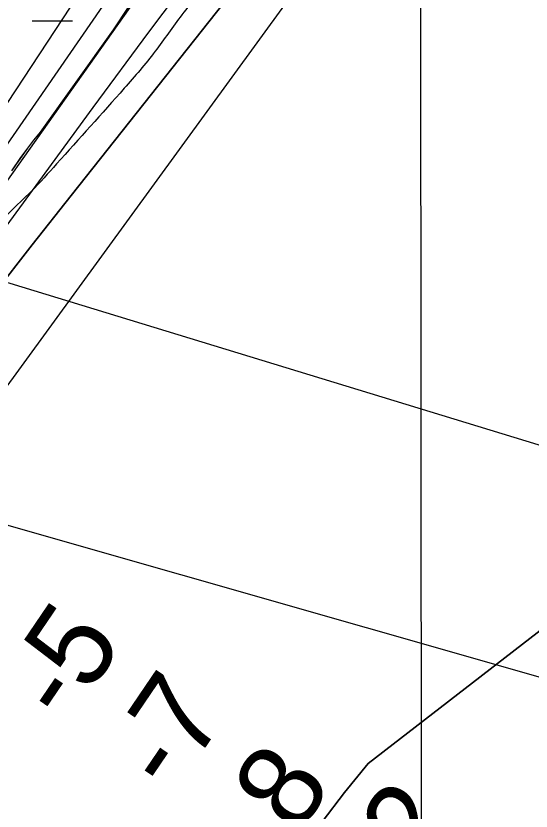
# Model space of a CAD drawing. Extents: x 3297735 to 3335592, y 670436 to 695807.
# Drawn here: x 3317296 to 3317704, y 689991 to 690622 of the extents above; entities that cross this region are included whole.
import ezdxf

# ---------------------------------------------------------------- set-up
doc = ezdxf.new("R2010")
doc.units = 0
for name, color, linetype in [('V-GRID-MAJR', 7, 'Continuous'), ('V-RIVR-EDGE', 7, 'Continuous'), ('V-RIVR-RANG', 7, 'Continuous'), ('V-SITE-VEGE', 7, 'Continuous'), ('V-TOPO-DPTH', 7, 'Continuous'), ('V-TOPO-MINR', 7, 'Continuous'), ('V-TOPO-WATR', 7, 'Continuous'), ('V-UTIL-LINE', 7, 'Continuous'), ('V-WETL-SWMP', 7, 'Continuous')]:
    doc.layers.add(name, color=color, linetype=linetype)

msp = doc.modelspace()

# ---------------------------------------------------------------- linework, layer by layer
at = {"layer": 'V-GRID-MAJR'}
msp.add_lwpolyline([(3317613.19, 694012.57), (3317614.99, 692249.17), (3317618.11, 689185.08), (3317621.45, 685897.36), (3317623.83, 683567.34), (3317626.56, 680885.93), (3317629.35, 678140.95), (3317631.33, 676194.39), (3317631.71, 675828.01)], dxfattribs=at)
at = {"layer": 'V-RIVR-EDGE'}
msp.add_spline([(3319555.14, 694014.55), (3319548.52, 694002.76), (3319539.36, 693985.79), (3319509.78, 693923.27), (3319496.46, 693903), (3319479.41, 693878.17), (3319464.01, 693854.58), (3319445.27, 693818.98), (3319424.44, 693775.51), (3319406.53, 693740.74), (3319395.69, 693713), (3319386.52, 693693.13), (3319372.79, 693671.61), (3319340.34, 693621.53), (3319316.61, 693580.14), (3319295.79, 693542.89), (3319282.06, 693520.96), (3319271.65, 693502.33), (3319267.89, 693489.49), (3319259.98, 693475.83), (3319250.42, 693465.08), (3319246.25, 693454.32), (3319237.93, 693442.32), (3319231.68, 693428.65), (3319225.43, 693414.99), (3319219.61, 693410.03), (3319205.47, 693391.42), (3319185.09, 693363.28), (3319164.7, 693327.69), (3319143.08, 693301.21), (3319109.39, 693253.21), (3319083.6, 693218.46), (3319061.14, 693187.85), (3319039.52, 693157.64), (3319018.29, 693123.29), (3318994.59, 693091.02), (3318949.68, 693031.86), (3318931.37, 693004.55), (3318913.08, 692981.38), (3318902.25, 692962.76), (3318892.68, 692944.55), (3318876.03, 692916.4), (3318861.86, 692887.84), (3318841.46, 692848.51), (3318822.29, 692807.53), (3318806.46, 692774.41), (3318803.1, 692758.66), (3318804.31, 692744.98), (3318808.02, 692734.61), (3318808.84, 692730.46), (3318817.11, 692725.47), (3318826.63, 692719.23), (3318832.83, 692713), (3318835.72, 692705.53), (3318835.27, 692692.27), (3318829.85, 692681.5), (3318819.88, 692669.09), (3318809.47, 692651.3), (3318783.24, 692602.87), (3318768.67, 692580.52), (3318760.79, 692575.98), (3318753.73, 692573.1), (3318747.11, 692573.94), (3318739.24, 692579.76), (3318735.53, 692585.58), (3318730.56, 692588.49), (3318721.44, 692588.1), (3318700.27, 692573.64), (3318679.48, 692549.66), (3318660.76, 692522.35), (3318646.6, 692493.37), (3318637.03, 692477.64), (3318624.96, 692456.95), (3318607.08, 692434.19), (3318599.98, 692413.49), (3318583.3, 692372.49), (3318565.82, 692342.28), (3318547.09, 692313.73), (3318534.2, 692295.52), (3318512.56, 692258.69), (3318488.02, 692224.76), (3318446.4, 692155.23), (3318418.11, 692112.61), (3318397.31, 692084.47), (3318386.91, 692066.68), (3318376.5, 692048.05), (3318354.44, 692011.22), (3318333.22, 691976.45), (3318316.13, 691940.02), (3318301.57, 691917.67), (3318275.38, 691884.99), (3318265.81, 691873), (3318250.82, 691844.85), (3318236.64, 691808.41), (3318222.07, 691781.09), (3318194.96, 691714.01), (3318179.96, 691684.2), (3318162.07, 691654.82), (3318140.84, 691619.64), (3318130.44, 691603.92), (3318120.89, 691595.24), (3318105.09, 691577.87), (3318090.12, 691558.42), (3318067.68, 691532.37), (3318043.56, 691501.75), (3318020.26, 691465.75), (3317998.21, 691433.06), (3317973.66, 691392.92), (3317962.42, 691371.81), (3317929.95, 691315.1), (3317907.9, 691282.41), (3317889.2, 691263.39), (3317870.48, 691238.16), (3317844.7, 691202.99), (3317833.05, 691186.02), (3317808.09, 691148.78), (3317780.64, 691109.47), (3317756.1, 691076.38), (3317731.98, 691045.35), (3317684.57, 690978.73), (3317668.76, 690954.73), (3317646.3, 690922.04), (3317635.48, 690907.15), (3317629.25, 690900.53), (3317620.1, 690889.36), (3317608.46, 690874.47), (3317601.4, 690867.03), (3317592.67, 690860.42), (3317585.59, 690845.93), (3317576.86, 690836), (3317565.64, 690821.11), (3317549.42, 690801.25), (3317522.4, 690767.75), (3317502.45, 690745), (3317489.97, 690727.62), (3317482.47, 690713.55), (3317479.54, 690701.12), (3317475.78, 690689.94), (3317474.94, 690683.31), (3317467.87, 690674.21), (3317451.65, 690653.94), (3317427.54, 690622.91), (3317406.33, 690593.95), (3317381.8, 690564.58), (3317328.18, 690504.62), (3317308.23, 690483.11), (3317290.78, 690466.16), (3317272.5, 690446.31), (3317248.81, 690422.74), (3317230.94, 690402.48), (3317202.23, 690356.54), (3317170.21, 690314.34), (3317129.47, 690266.36), (3317099.12, 690227.48), (3317085.82, 690212.59), (3317074.19, 690204.33), (3317063.38, 690189.85), (3317045.08, 690163.78), (3317020.95, 690128.61), (3316996.82, 690093.85), (3316970.63, 690059.1), (3316926.98, 690008.23), (3316891.65, 689970.6), (3316861.71, 689930.05), (3316828.03, 689887.86), (3316809.31, 689860.13), (3316797.25, 689841.93), (3316783.53, 689825.38), (3316737.37, 689762.08), (3316714.9, 689728.98), (3316681.64, 689687.61), (3316661.69, 689665.69), (3316647.97, 689646.66), (3316619.68, 689606.11), (3316602.63, 689581.28), (3316583.49, 689551.9), (3316563.93, 689519.62), (3316547.71, 689499.35), (3316541.89, 689491.9), (3316538.57, 689488.6), (3316532.31, 689474.1), (3316523.16, 689461.28), (3316509.03, 689445.15), (3316500.29, 689431.49), (3316493.22, 689419.9), (3316485.73, 689407.9), (3316486.11, 689397.12), (3316486.48, 689375.57), (3316487.29, 689371.01), (3316491.44, 689370.17), (3316493.5, 689366.43), (3316494.29, 689352.75), (3316496.75, 689341.56), (3316502.54, 689336.57), (3316504.2, 689334.08), (3316504.18, 689328.69), (3316501.27, 689325.8), (3316488.83, 689321.27), (3316487.17, 689319.61), (3316487.16, 689316.71), (3316492.96, 689316.7), (3316502.08, 689318.33), (3316508.3, 689318.32), (3316513.27, 689314.99), (3316516.58, 689314.98), (3316524.87, 689314.55), (3316535.62, 689303.33), (3316544.71, 689293.36), (3316545.54, 689290.04), (3316543.46, 689287.97), (3316525.66, 689296.72), (3316509.92, 689304.22), (3316502.06, 689307.14), (3316490.45, 689308.41), (3316482.58, 689308.02), (3316478.02, 689308.03), (3316473.47, 689311.77), (3316449.46, 689323.85), (3316424.59, 689324.74), (3316401.79, 689323.14), (3316381.47, 689318.22), (3316366.54, 689316.18), (3316352.85, 689311.24), (3316334.16, 689295.54), (3316302.2, 689277.79), (3316275.21, 689257.14), (3316266.49, 689249.28), (3316249.02, 689224.04), (3316230.28, 689191.76), (3316217.78, 689162.78), (3316200.69, 689125.93), (3316182.37, 689092.82), (3316162.8, 689054.73), (3316141.17, 689024.94), (3316114.57, 688996.41), (3316081.77, 688971.62), (3316036.89, 688926.14), (3316007.39, 688897.61), (3315987.04, 688880.67), (3315970.01, 688865.79), (3315959.63, 688858.77), (3315957.13, 688852.14), (3315955.46, 688848.42), (3315953.91, 688835.53)], degree=3, dxfattribs=at)
at = {"layer": 'V-SITE-VEGE'}
for p, q in [((3317385, 690629.03), (3317373.06, 690610.88)), ((3317373.06, 690610.88), (3317315.17, 690529.81)), ((3317315.17, 690529.81), (3317309.82, 690523.5)), ((3317309.82, 690523.5), (3317305.16, 690517.21)), ((3317305.16, 690517.21), (3317299.17, 690508.82)), ((3317299.17, 690508.82), (3317292.53, 690499.05))]:
    msp.add_line(p, q, dxfattribs=at)
at = {"layer": 'V-TOPO-DPTH'}
for points in [[(3318584.05, 691430.83), (3318517.47, 691277.69), (3318508.35, 691257.27), (3318498.95, 691236.97), (3318489.16, 691216.87), (3318479.09, 691196.89), (3318269.71, 690647.74), (3318256.86, 690622.59), (3318208.48, 690534.96), (3318203.12, 690525.89), (3318197.41, 690517.06), (3318191.18, 690508.59), (3318184.6, 690500.35), (3317575.1, 690028.99), (3317556.52, 690006.11), (3317538.65, 689982.71)], [(3316793, 689774.85), (3317107.27, 690178.86), (3317132.19, 690210.99), (3317157.04, 690243.18), (3317181.79, 690275.45), (3317206.47, 690307.76), (3317217.54, 690322.29), (3317247.81, 690361.83), (3317278.24, 690401.24), (3317308.89, 690440.49), (3317339.69, 690479.61), (3317615.66, 690828.12), (3317637.07, 690855.24), (3317658.45, 690882.38), (3317679.77, 690909.57), (3317701.05, 690936.79), (3317713.85, 690953.21), (3317741.25, 690988.86), (3317768.29, 691024.76), (3317794.82, 691061.05), (3317821, 691097.59), (3318051.03, 691423.54)], [(3316793, 689774.85), (3317107.27, 690178.86), (3317132.19, 690210.99), (3317157.04, 690243.18), (3317181.79, 690275.45), (3317206.47, 690307.76), (3317217.54, 690322.29), (3317247.81, 690361.83), (3317278.24, 690401.24), (3317308.89, 690440.49), (3317339.69, 690479.61), (3317615.66, 690828.12), (3317637.07, 690855.24), (3317658.45, 690882.38), (3317679.77, 690909.57), (3317701.05, 690936.79), (3317713.85, 690953.21), (3317741.25, 690988.86), (3317768.29, 691024.76), (3317794.82, 691061.05), (3317821, 691097.59), (3318051.03, 691423.54)], [(3317973.77, 691365.46), (3317926.73, 691301.65), (3317878.02, 691239.19), (3317612.68, 690948.39), (3317599.66, 690931.96), (3317597.18, 690928.75), (3317594.74, 690925.52), (3317592.36, 690922.23), (3317590.04, 690918.91), (3317565.66, 690883.36), (3317551.13, 690862.28), (3317536.54, 690841.24), (3317521.84, 690820.27), (3317507.09, 690799.34), (3317153.43, 690300.28), (3317140.28, 690281.94), (3317126.99, 690263.69), (3317113.51, 690245.59), (3317099.89, 690227.58), (3317000.42, 690097.58), (3316950.45, 690033.27), (3316899.86, 689969.46)], [(3317394.87, 689755.58), (3317505.72, 689933.86), (3317521.83, 689958.54), (3317538.65, 689982.71), (3317556.52, 690006.11), (3317575.1, 690028.99), (3318184.6, 690500.35), (3318191.18, 690508.59), (3318197.41, 690517.06), (3318203.12, 690525.89), (3318208.48, 690534.96), (3318256.86, 690622.59), (3318269.71, 690647.74), (3318429.31, 691066.33), (3318749.01, 690994.64)]]:
    msp.add_lwpolyline(points, dxfattribs=at)
at = {"layer": 'V-TOPO-MINR'}
for points in [[(3318046.49, 691444.53), (3317923.05, 691270.33), (3317876.82, 691206.85), (3317829.53, 691144.18), (3317780.65, 691082.75), (3317730.71, 691022.14), (3317672.06, 690952.8), (3317650.77, 690927.38), (3317629.64, 690901.83), (3317608.75, 690876.08), (3317588.02, 690850.2), (3317536.92, 690785.76), (3317491.12, 690727.29), (3317445.77, 690668.48), (3317401.11, 690609.14), (3317356.9, 690549.45), (3317177.25, 690303.88), (3317158.99, 690279.1), (3317140.6, 690254.4), (3317122.05, 690229.84), (3317103.37, 690205.36), (3316898.23, 689938.45)], [(3318080.81, 691434.23), (3317690.27, 690875.42), (3317687.94, 690872.13), (3317685.57, 690868.86), (3317684.38, 690867.24), (3317681.94, 690864.03), (3317680.7, 690862.44), (3317659.18, 690835.01), (3317647.25, 690819.65), (3317635.44, 690804.2), (3317623.79, 690788.62), (3317612.25, 690772.96), (3317240.33, 690262.37), (3317221.88, 690236.94), (3317203.49, 690211.47), (3317185.2, 690185.93), (3317166.97, 690160.34), (3317026.02, 689961.69)], [(3318584.05, 691430.83), (3318517.47, 691277.69), (3318508.35, 691257.27), (3318498.95, 691236.97), (3318489.16, 691216.87), (3318479.09, 691196.89), (3318269.71, 690647.74), (3318256.86, 690622.59), (3318208.48, 690534.96), (3318203.12, 690525.89), (3318197.41, 690517.06), (3318191.18, 690508.59), (3318184.6, 690500.35), (3317575.1, 690028.99), (3317556.52, 690006.11), (3317538.65, 689982.71)], [(3317944.27, 691371.95), (3317571.06, 690977.16), (3317553.45, 690953.44), (3317536.47, 690929.27), (3317519.92, 690904.79), (3317282.87, 690544.01), (3317253.48, 690499.62), (3317223.87, 690455.37), (3317193.96, 690411.33), (3317163.83, 690367.44), (3317112.37, 690293.04), (3317107.77, 690286.49), (3317103.1, 690279.98), (3317098.33, 690273.55), (3317093.49, 690267.17), (3317064.01, 690228.89), (3317044.25, 690203.51), (3317024.3, 690178.28), (3317004.08, 690153.27), (3316983.67, 690128.41), (3316667.77, 689747.87)], [(3317973.77, 691365.46), (3317926.73, 691301.65), (3317878.02, 691239.19), (3317612.68, 690948.39), (3317599.66, 690931.96), (3317597.18, 690928.75), (3317594.74, 690925.52), (3317592.36, 690922.23), (3317590.04, 690918.91), (3317565.66, 690883.36), (3317551.13, 690862.28), (3317536.54, 690841.24), (3317521.84, 690820.27), (3317507.09, 690799.34), (3317153.43, 690300.28), (3317140.28, 690281.94), (3317126.99, 690263.69), (3317113.51, 690245.59), (3317099.89, 690227.58), (3317000.42, 690097.58), (3316950.45, 690033.27), (3316899.86, 689969.46)], [(3317920.82, 691316.91), (3317594.38, 690966.26), (3317584.1, 690952.96), (3317574.05, 690939.51), (3317564.31, 690925.82), (3317554.79, 690911.98), (3317469.38, 690784.54), (3317417.1, 690707.01), (3317364.5, 690629.7), (3317311.45, 690552.69), (3317258.1, 690475.89), (3317132.82, 690296.72), (3317123.98, 690284.24), (3317115.02, 690271.85), (3317105.9, 690259.58), (3317096.67, 690247.39), (3317039.59, 690173.02), (3317001.42, 690123.96), (3316962.83, 690075.24), (3316923.61, 690027.01), (3316883.98, 689979.13)]]:
    msp.add_lwpolyline(points, dxfattribs=at)
at = {"layer": 'V-TOPO-WATR'}
msp.add_lwpolyline([(3318051.03, 691423.54), (3317821, 691097.59), (3317794.82, 691061.05), (3317768.29, 691024.76), (3317741.25, 690988.86), (3317713.85, 690953.21), (3317701.05, 690936.79), (3317679.77, 690909.57), (3317658.45, 690882.38), (3317637.07, 690855.24), (3317615.66, 690828.12), (3317339.69, 690479.61), (3317308.89, 690440.49), (3317278.24, 690401.24), (3317247.81, 690361.83), (3317217.54, 690322.29), (3317206.47, 690307.76), (3317181.79, 690275.45), (3317157.04, 690243.18), (3317132.19, 690210.99), (3317107.27, 690178.86), (3316793, 689774.85)], dxfattribs=at)
at = {"layer": 'V-UTIL-LINE'}
for p, q in [((3320794.04, 689217.49), (3315626.29, 690692.6)), ((3317160.85, 690449.7), (3320488.36, 689432.64))]:
    msp.add_line(p, q, dxfattribs=at)
at = {"layer": 'V-WETL-SWMP'}
for p, q in [((3317384.98, 690629.03), (3317377.68, 690617.87)), ((3317308.7, 690618.2), (3317340.7, 690618.2)), ((3317377.68, 690617.87), (3317373.04, 690610.89)), ((3317373.04, 690610.89), (3317315.15, 690529.82)), ((3317315.15, 690529.82), (3317309.8, 690523.51)), ((3317309.8, 690523.51), (3317305.14, 690517.22)), ((3317305.14, 690517.22), (3317299.15, 690508.83)), ((3317299.15, 690508.83), (3317292.51, 690499.06))]:
    msp.add_line(p, q, dxfattribs=at)

# ---------------------------------------------------------------- texts
at = {"layer": 'V-RIVR-RANG'}
for s, p in [('-5', (3317336.97, 690058.87)), ('-7', (3317420.31, 690003.59)), ('-8', (3317502.77, 689947.02)), ('-12', (3317575.6, 689876.25))]:
    msp.add_text(s, height=67, rotation=55.83514, dxfattribs=at).set_placement(p)

doc.saveas('drawing.dxf')
